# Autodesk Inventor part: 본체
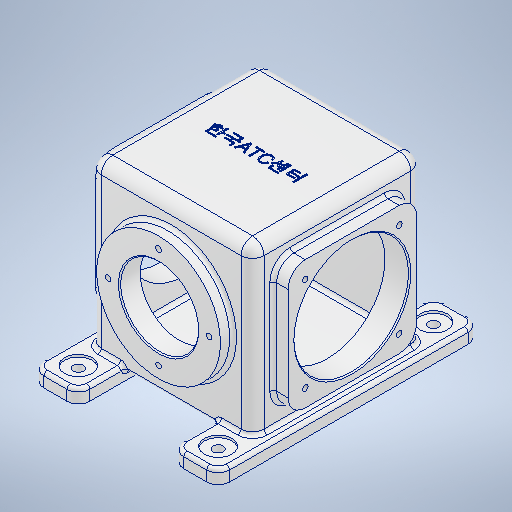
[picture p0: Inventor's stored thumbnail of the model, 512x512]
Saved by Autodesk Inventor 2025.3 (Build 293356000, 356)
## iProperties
Created: 2026-01
Part Number: 본체
Material: 알루미늄 6061
Document SubType Name: Modeling
Designer: PC-13
Density: 2.7 g/cm^3
Appearance: 알루미늄 - 평지
Mass: 2882.07 g
Surface Area: 2447.66 cm^2
Volume: 1067.43 cm^3
Author: PC-13
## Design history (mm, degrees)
sketch "스케치1"
  geometry: L1 (71, -114)-(51, -114); L2 (41, -104)-(41, 104); L3 (51, 114)-(71, 114); L4 (81, 104)-(81, -104); L5 (0, -162.499)-(0, 162.499) reference; L6 (-41, -104)-(-41, 104); L7 (-51, 114)-(-71, 114); L8 (-81, 104)-(-81, -104); L9 (-71, -114)-(-51, -114); L10 (116.299, 0)-(-116.299, 0) reference; A1 r 10 centre (71, -104) between (71, -114) and (81, -104); A2 r 10 centre (51, -104) between (41, -104) and (51, -114); A3 r 10 centre (71, 104) between (81, 104) and (71, 114); A4 r 10 centre (51, 104) between (51, 114) and (41, 104); A5 r 10 centre (-51, 104) between (-41, 104) and (-51, 114); A6 r 10 centre (-71, 104) between (-71, 114) and (-81, 104); A7 r 10 centre (-51, -104) between (-51, -114) and (-41, -104); A8 r 10 centre (-71, -104) between (-81, -104) and (-71, -114); 8 further points
  constraints: 16 end point, 16 point on circle, 16 point on line, 16 tangent, 8 centre point, 7 equal radius, 4 symmetric about line, 2 parallel, 1 horizontal, 1 perpendicular, 1 other
  dimensions: "d5" = 162 distance between parallel lines of L8 L4; "d6" = 40 distance between parallel lines of L2 L4; "d7" = 228 distance between parallel lines of L3 L1; "d8" = 10 radius of A1
extrude "돌출1" new body sketch "스케치1" distance "d9" = 12; taper "d10" = 0 deg
sketch "스케치2"
  geometry: L1 (-71, 156)-(71, 156); L2 (71, 156)-(71, 8); L3 (71, 8)-(-71, 8); L4 (-71, 8)-(-71, 156); L5 (0, -31.2)-(0, 187.2) reference; 1 further point
  constraints: 8 end point, 2 parallel, 1 horizontal, 1 perpendicular, 1 other
  dimensions: "d11" = 156 distance from line of point (0, 0) L1; "d12" = 142 distance between parallel lines of L2 L4; "d13" = 8 distance from line of point (0, 0) L3
extrude "돌출2" join sketch "스케치2" stored distance "d14" = 148; taper "d15" = 0 deg
sketch "스케치3"
  geometry: L1 (-130, 126)-(-18, 126); L2 (-18, 126)-(-18, 14); L3 (-18, 14)-(-130, 14); L4 (-130, 14)-(-130, 126); L5 (-178, -12)-(30, -12) reference; 3 further points
  constraints: 8 end point, 3 midpoint, 2 parallel, 1 horizontal, 1 perpendicular, 1 vertical alignment
  dimensions: "d18" = 112 distance of L2.end L3.end; "d19" = 112 distance of L1.end L2.end; "d20" = 82 vertical distance of point (-74, -12) point (-18, 70)
extrude "돌출3" join sketch "스케치3" distance "d21" = 13; taper "d22" = 0 deg
sketch "스케치4"
  geometry: C1 r 50 at (-74, 70); 1 further point
  constraints: 1 centre point, 1 vertical alignment
  dimensions: "d23" = 100 diameter of C1; "d24" = 82 distance of point (-74, -12) C1.centre
extrude "돌출4" cut sketch "스케치4" extent not by distance; stored distance "d25" = 0; taper "d26" = 0 deg
fillet "모깎기1" dims "d27" = 15
sketch "스케치6"
  geometry: L1 (-115, 29)-(-33, 29); L2 (-33, 29)-(-33, 111); L3 (-33, 111)-(-115, 111); L4 (-115, 111)-(-115, 29); L5 (-115, 29)-(-33, 111); L6 (-33, 29)-(-115, 111); 6 further points
  constraints: 12 end point, 4 coincident, 2 midpoint, 2 parallel, 1 horizontal, 1 perpendicular, 1 vertical alignment
  dimensions: "d46" = 82 distance of L3.end L2.end; "d47" = 82 distance of L2.end L1.end; "d48" = 82 distance of point (-74, -12) point (-74, 70)
hole "구멍2" sketch "스케치6" at (-115, 111), (-33, 111), (-33, 29), (-115, 29) diameter "d39" = 4.917; stored, may be unused: countersink angle "d43" = 90 deg, drill point angle "d45" = 118 deg; dims "d40" = 12, "d41" = 4, "d42" = 2, "d44" = 14
sketch "스케치7"
  geometry: C1 r 54 at (0, 82); C2 r 34 at (0, 82); 1 further point
  constraints: 2 centre point, 1 coincident, 1 vertical alignment
  dimensions: "d49" = 108 diameter of C1; "d50" = 82 distance of point (0, 0) C1.centre; "d51" = 68 diameter of C2
extrude "돌출5" join sketch "스케치7" distance "d52" = 11; taper "d53" = 0 deg
extrude "돌출6" cut sketch "스케치7" stored distance "d54" = 11; taper "d55" = 0 deg
sketch "스케치8" dims "d63" = 88
  geometry: C1 r 34 at (0, 0) reference; 3 further points
  constraints: 2 vertical alignment, 3 other
hole "구멍3" sketch "스케치8" at (0, 44) diameter "d56" = 4.917; stored, may be unused: countersink angle "d60" = 90 deg, drill point angle "d62" = 118 deg; dims "d57" = 12, "d58" = 4, "d59" = 2, "d61" = 14
sketch "스케치9"
  geometry: L1 (-113.4, 0)-(113.4, 0) reference; L2 (0, 159.6)-(0, -159.6) reference; 5 further points
  constraints: 2 horizontal alignment, 2 symmetric about line, 2 vertical alignment
  dimensions: "d74" = 188 distance of point (61, -94) point (61, 94); "d75" = 122 distance of point (61, -94) point (-61, -94)
hole "구멍4" sketch "스케치9" at (61, -94), (-61, -94), (61, 94), (-61, 94) diameter "d67" = 9; stored, may be unused: countersink angle "d71" = 90 deg, drill point angle "d73" = 118 deg; dims "d68" = 12, "d69" = 24, "d70" = 2, "d72" = 14
chamfer "모따기1" distance "d76" = 1; stored, may be unused: second distance "d77" = 2, angle "d78" = 45 deg
fillet "모깎기2" dims "d79" = 3
fillet "모깎기3" dims "d80" = 10
fillet "모깎기4" dims "d81" = 3
fillet "모깎기5" dims "d82" = 3
node "작업 평면1"
sketch "스케치11"
  geometry: L1 (122, 0)-(122, -128) reference; L2 (0, 0)-(122, 0) reference; L3 (0, -128)-(0, 0) reference; L4 (122, -128)-(0, -128) reference; 2 further points
  constraints: 1 coincident, 1 other
feature "엠보싱1" sketch "스케치11" dims "d5" = 162, "d6" = 40, "d7" = 228, "d8" = 10, "d84" = 0.5, "d85" = 0
sketch "스케치12"
  geometry: L1 (156, 64)-(156, -64) reference; L2 (146, -74)-(15, -74) reference; L3 (9, -74)-(15, -74) reference; L4 (8, -77)-(8, 77) reference; L5 (9, -74)-(8, -74) reference; L6 (15, 74)-(146, 74) reference; L7 (15, 74)-(9, 74) reference; L8 (8, 74)-(9, 74) reference; L9 (15, 67)-(146, 67); L10 (149, 64)-(149, -64); L11 (146, -67)-(15, -67); L12 (15, -67)-(15, 67); A1 r 10 centre (146, 64) between (156, 64) and (146, 74) reference; A2 r 10 centre (146, -64) between (146, -74) and (156, -64) reference; A3 r 3 centre (146, 64) between (149, 64) and (146, 67); A4 r 3 centre (146, -64) between (146, -67) and (149, -64); 1 further point
  constraints: 10 end point, 4 point on circle, 2 centre point, 1 parallel, 4 other
  dimensions: "d88" = 7 distance between parallel lines of L10 L1; "d89" = 7 distance between parallel lines of L4 L12
extrude "돌출7" cut sketch "스케치12" stored distance "d90" = 125; taper "d91" = 0 deg
fillet "모깎기6" dims "d92" = 3
fillet "모깎기7" dims "d93" = 3
chamfer "모따기2" distance "d94" = 1; stored, may be unused: second distance "d95" = 2, angle "d96" = 45 deg
node "솔리드1"
pattern_circular "원형 패턴1" dims angle "d65" = 360 deg
mirror "미러2"
node "투영된 루프2"
feature "A9D066F2-1C7D-4E18-AEED-F7BC21143FA4" dims "d56" = 4.917, "d57" = 12, "d58" = 4, "d59" = 2, "d60" = 90 deg, "d61" = 14, "d62" = 118 deg
other parameters: "d83" = 51.75, "d87" = 7
